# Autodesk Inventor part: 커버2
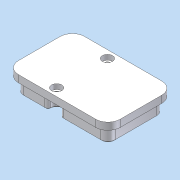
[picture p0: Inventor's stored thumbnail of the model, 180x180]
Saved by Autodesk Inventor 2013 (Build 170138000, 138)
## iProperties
Company: 한국ATC센터
Created: 2015-04
Part Number: 커버2
Document SubType Name: Modeling
Designer: KYOUNG IL JANG
Density: 2.71 g/cm^3
Material: 알루미늄 6061
Mass: 222.992 g
Surface Area: 213.51 cm^2
Volume: 82.2849 cm^3
Author: KYOUNG IL JANG
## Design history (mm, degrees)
node "작업 평면1"
sketch "스케치1"
  geometry: L1 (-16.986, 27.5)-(-38, 27.5) reference; L2 (-45, 20.5)-(-45, -20.5) reference; L3 (-38, -27.5)-(-16.986, -27.5) reference; L4 (0.986, -27.5)-(38, -27.5) reference; L5 (45, -20.5)-(45, 20.5) reference; L6 (38, 27.5)-(0.986, 27.5) reference; C1 r 25 at (15, 0); A1 r 3 centre (-16.986, 24.5) between (-13.991, 24.667) and (-16.986, 27.5) reference; A2 r 7 centre (-38, 20.5) between (-38, 27.5) and (-45, 20.5) reference; A3 r 7 centre (-38, -20.5) between (-45, -20.5) and (-38, -27.5) reference; A4 r 3 centre (-16.986, -24.5) between (-16.986, -27.5) and (-13.991, -24.667) reference; A5 r 6 centre (-8, -25) between (-2.009, -24.667) and (-13.991, -24.667) reference; A6 r 3 centre (0.986, -24.5) between (-2.009, -24.667) and (0.986, -27.5) reference; A7 r 7 centre (38, -20.5) between (38, -27.5) and (45, -20.5) reference; A8 r 7 centre (38, 20.5) between (45, 20.5) and (38, 27.5) reference; A9 r 3 centre (0.986, 24.5) between (0.986, 27.5) and (-2.009, 24.667) reference; A10 r 6 centre (-8, 25) between (-13.991, 24.667) and (-2.009, 24.667) reference; 1 further point
  constraints: 20 point on circle, 12 end point, 11 centre point, 4 horizontal, 2 vertical, 36 other
extrude "돌출1" new body sketch "스케치1" distance "d0" = 14; taper "d1" = 0 deg
sketch "스케치2"
  geometry: L1 (38, -32.5)-(-38, -32.5) reference; L2 (50, 20.5)-(50, -20.5) reference; L3 (-38, 32.5)-(38, 32.5) reference; L4 (-50, -20.5)-(-50, 20.5) reference; A1 r 12 centre (38, -20.5) between (38, -32.5) and (50, -20.5) reference; A2 r 12 centre (38, 20.5) between (50, 20.5) and (38, 32.5) reference; A3 r 12 centre (-38, 20.5) between (-38, 32.5) and (-50, 20.5) reference; A4 r 12 centre (-38, -20.5) between (-50, -20.5) and (-38, -32.5) reference; 1 further point
extrude "돌출2" join sketch "스케치2" distance "d2" = 7; taper "d3" = 0 deg
sketch "스케치3"
  geometry: C1 r 2.458 at (-8, 25) reference; C2 r 2.458 at (-8, -25) reference; 1 further point
hole "구멍1" sketch "스케치3" at (-8, -25), (-8, 25) diameter "d4" = 6; stored, may be unused: countersink angle "d8" = 90 deg, drill point angle "d10" = 118 deg; dims "d5" = 6, "d6" = 10, "d7" = 5, "d9" = 8
fillet "모깎기1" dims "d11" = 0.3
chamfer "모따기1" distance "d12" = 1; stored, may be unused: second distance "d13" = 2, angle "d14" = 45 deg
node "솔리드1"
node "참조2"
node "참조3"
node "참조4"
node "참조5"
node "참조6"
node "참조7"
node "참조8"
node "참조9"
node "참조10"
node "참조11"
